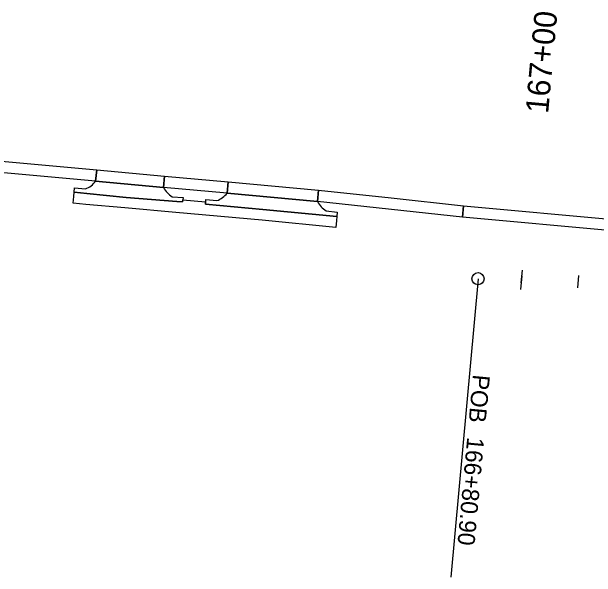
# Model space of a CAD drawing. Extents: x 20499216 to 20505321, y 7953487 to 7960535.
# Drawn here: x 20500189.2 to 20500446.4, y 7953879.2 to 7954128.2 of the extents above; entities that cross this region are included whole.
import ezdxf

# ---------------------------------------------------------------- set-up
doc = ezdxf.new("R2010")
doc.units = 0
for name, color, linetype in [('EXT_CU', 7, 'Continuous'), ('EXT_RR', 7, 'Continuous'), ('NamedBoundary', 7, 'Continuous'), ('Natural', 7, 'Continuous'), ('Safety', 7, 'Continuous')]:
    doc.layers.add(name, color=color, linetype=linetype)

msp = doc.modelspace()

# ---------------------------------------------------------------- linework, layer by layer
at = {"layer": 'EXT_CU'}
for points in [[(20500226.62, 7954058.59), (20500226.17, 7954053.61), (20500080.73, 7954066.82), (20500081.18, 7954071.8)], [(20500226.17, 7954053.61), (20500226.62, 7954058.59), (20500256.5, 7954055.85), (20500256.04, 7954050.87)], [(20500256.04, 7954050.87), (20500256.5, 7954055.85), (20500284.43, 7954053.29), (20500283.97, 7954048.31)], [(20500324.26, 7954049.63), (20500323.8, 7954044.65), (20500283.97, 7954048.31), (20500284.43, 7954053.29)], [(20500455.16, 7954031.55), (20500387.57, 7954037.77), (20500388.03, 7954042.75), (20500455.61, 7954036.53), (20500458.58, 7954036.27), (20500458.14, 7954031.29)]]:
    msp.add_lwpolyline(points, close=True, dxfattribs=at)
msp.add_lwpolyline([(20500323.8, 7954044.65), (20500324.27, 7954049.63), (20500356.15, 7954046.19), (20500388.03, 7954042.75), (20500387.57, 7954037.77), (20500387.54, 7954037.77), (20500323.8, 7954044.65)], dxfattribs=at)
msp.add_arc((20500332.79, 7954049.04), 10, 206.008, 206.0117, dxfattribs=at)
at = {"layer": 'EXT_RR'}
for p, q in [((20500413.68, 7954011.96), (20500413.12, 7954005.86)), ((20500438.3, 7954006.63), (20500438.8, 7954012.07))]:
    msp.add_line(p, q, dxfattribs=at)
at = {"layer": 'NamedBoundary'}
for p, q in [((20500226.17, 7954053.61), (20500256.04, 7954050.87)), ((20500283.97, 7954048.31), (20500323.8, 7954044.65))]:
    msp.add_line(p, q, dxfattribs=at)
for points in [[(20500259.87, 7954046.76), (20500264.61, 7954046.36), (20500264.45, 7954044.46), (20500261.92, 7954044.69), (20500239.54, 7954046.4), (20500222.36, 7954048.23), (20500216.69, 7954048.75), (20500216.85, 7954050.61), (20500221.68, 7954050.2)], [(20500327.53, 7954040.53), (20500332.46, 7954040.02), (20500332.27, 7954038.08), (20500299.74, 7954041.14), (20500274.43, 7954043.52), (20500274.61, 7954045.46), (20500279.55, 7954045.04)]]:
    msp.add_lwpolyline(points, dxfattribs=at)
msp.add_lwpolyline([(20500274.52, 7954044.5), (20500274.43, 7954043.52), (20500299.74, 7954041.14), (20500332.27, 7954038.08), (20500332.1, 7954036.25), (20500331.81, 7954033.26), (20500299.37, 7954036.41), (20500261.45, 7954039.86), (20500239.04, 7954041.83), (20500221.79, 7954043.31), (20500216.24, 7954043.84), (20500216.52, 7954046.82), (20500216.69, 7954048.75), (20500222.36, 7954048.23), (20500239.54, 7954046.4), (20500261.92, 7954044.69), (20500264.45, 7954044.46), (20500264.53, 7954045.4)], close=True, dxfattribs=at)
for centre, start, end in [((20500218.11, 7954059.54), 290.882, 323.6571), ((20500264.98, 7954055.36), 206.6611, 239.3011), ((20500276.04, 7954054.4), 290.5796, 322.464), ((20500332.79, 7954049.04), 206.008, 238.2773)]:
    msp.add_arc(centre, 10, start, end, dxfattribs=at)
at = {"layer": 'Natural'}
for p in [(20500394.39, 7954010.65), (20500382.36, 7953879.2)]:
    msp.add_line(p, (20500382.36, 7953879.2), dxfattribs=at)
msp.add_circle((20500394.39, 7954010.65), 2.67, dxfattribs=at)
at = {"layer": 'Safety'}
msp.add_line((20500413.4, 7954008.91), (20500413.9, 7954014.35), dxfattribs=at)

# ---------------------------------------------------------------- texts
at = {"layer": 'EXT_RR'}
msp.add_text('167+00', height=10.02, rotation=84.7714, dxfattribs=at).set_placement((20500425.23, 7954083.14))
at = {"layer": 'Natural'}
for s, p in [('POB ', (20500392.2, 7953968.68)), ('166+80.90', (20500389.67, 7953941.08))]:
    msp.add_text(s, height=7.5, rotation=264.7714, dxfattribs=at).set_placement(p)

doc.saveas('drawing.dxf')
